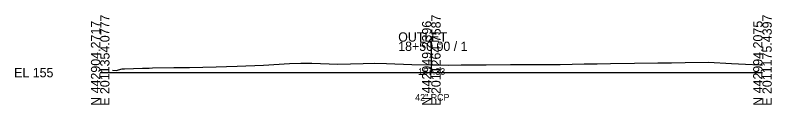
# Model space of a CAD drawing. Extents: x -26 to 1203, y -15 to 9526.
# Drawn here: x -25.7 to 202.8, y 8490.3 to 8517.3 of the extents above; entities that cross this region are included whole.
import ezdxf

# ---------------------------------------------------------------- set-up
doc = ezdxf.new("R2010")
doc.units = 0
for name, color, linetype in [('Exist Cross Section Cell', 7, 'Continuous'), ('Exist XS Center Line Elevation Label', 7, 'Continuous'), ('Exist XS Ground Line', 7, 'Continuous'), ('Prop XSC Text', 7, 'Continuous')]:
    doc.layers.add(name, color=color, linetype=linetype)

msp = doc.modelspace()

# ---------------------------------------------------------------- linework, layer by layer
at = {"layer": 'Exist Cross Section Cell'}
for p, q in [((100, 8500), (100, 8509.33)), ((0, 8500), (100, 8500)), ((100, 8500), (200, 8500))]:
    msp.add_line(p, q, dxfattribs=at)
at = {"layer": 'Exist XS Ground Line'}
msp.add_lwpolyline([(3.72, 8500.71), (4.77, 8500.64), (6.62, 8501.18), (7.3, 8501.17), (12.74, 8501.34), (14.75, 8501.39), (15.76, 8501.42), (22.2, 8501.54), (26.96, 8501.57), (34.98, 8501.76), (38.15, 8501.84), (41.37, 8501.95), (49.35, 8502.23), (57.21, 8502.71), (60.54, 8502.84), (63.92, 8502.81), (71.74, 8502.59), (79.45, 8502.77), (82.94, 8502.82), (86.47, 8502.71), (94.13, 8502.42), (100, 8502.33), (101.69, 8502.31), (105.33, 8502.23), (109.02, 8502.31), (116.52, 8502.39), (123.93, 8502.45), (127.72, 8502.45), (131.56, 8502.48), (138.92, 8502.49), (146.17, 8502.62), (150.11, 8502.69), (154.11, 8502.74), (161.31, 8502.85), (168.41, 8502.91), (172.5, 8502.95), (176.66, 8503.03), (183.7, 8503.11), (190.64, 8502.78), (194.89, 8502.57), (199.2, 8502.39), (200, 8502.37)], dxfattribs=at)

# ---------------------------------------------------------------- texts
at = {"layer": 'Exist Cross Section Cell'}
for s, p in [('N 442904.2717', (0, 8490)), ('E 2011354.0777', (2.8, 8490)), ('N 442949.2396', (100, 8490)), ('E 2011264.7587', (102.8, 8490)), ('N 442994.2075', (200, 8490)), ('E 2011175.4397', (202.8, 8490))]:
    msp.add_text(s, height=2.8, rotation=90, dxfattribs=at).set_placement(p)
for s, p in [('OUTLET', (90, 8509.33)), ('18+50.00 / 1', (90, 8506.53)), ('EL 155', (-26, 8498.6))]:
    msp.add_text(s, height=2.8, dxfattribs=at).set_placement(p)
at = {"layer": 'Exist XS Center Line Elevation Label'}
msp.add_text('157.33', height=2, dxfattribs=at).set_placement((95.99, 8499.33))
at = {"layer": 'Prop XSC Text'}
msp.add_text('42" RCP', height=2, dxfattribs=at).set_placement((95.14, 8491.54))

doc.saveas('drawing.dxf')
